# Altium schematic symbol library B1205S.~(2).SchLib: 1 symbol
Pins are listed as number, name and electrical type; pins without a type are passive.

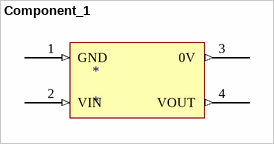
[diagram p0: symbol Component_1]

## Component_1
designator *
pins: 1 GND (in), 2 VIN (in), 3 0V (out), 4 VOUT (out)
